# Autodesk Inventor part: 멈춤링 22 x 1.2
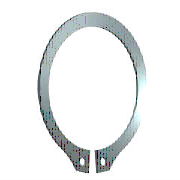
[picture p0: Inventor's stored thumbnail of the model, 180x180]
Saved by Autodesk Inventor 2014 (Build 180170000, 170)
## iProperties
IsCustomPart: 0
Created: 2009-02
Part Number: 멈춤링 22 x 1.2
Material: Steel, Mild
Description: 리테이닝 링(C형)
Document SubType Name: Modeling
Standard: KS B 1336
Designer: SeoGD™
Standards Organization: KS
Language: ko-KR
Size Designation: 22 x 1.2
Categories: <MemberInstance><Categories><Category DisplayName="샤프트 부품" InternalName="7f7aeb1f-a693-4053-b835-cee3144e0d98" Mnemonic="SHFT"><Category DisplayName="써클립" Inter
Density: 7.86 g/cm^3
Mass: 1.8286 g
Surface Area: 5.91219 cm^2
Volume: 0.232646 cm^3
Appearance: Metal-Steel
Author: SeoGD™
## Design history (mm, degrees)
sketch "스케치1"
  geometry: L1 (-6, 0)-(6, 0) reference; L2 (0, 20.189)-(0, -80.536) reference; L3 (-48.09, 0)-(48.09, 0) reference; L4 (-0.5, -21.488)-(-0.5, -25.588); L5 (-0.5, -6.54)-(-0.5, -13.29); L6 (-2.795, 2.7)-(3.672, 2.7); L7 (0.5, -6.54)-(0.5, -13.29); L8 (0.5, -21.488)-(0.5, -25.588); C1 r 1 at (-2, -23.437); C2 r 1 at (2, -23.437); A1 r 10.5 centre (0, -11) between (0.5, -21.488) and (-0.5, -21.488); A2 r 13.025 centre (0, -10.325) between (5.149, -22.289) and (-5.149, -22.289); A3 r 14.597 centre (0, -11) between (-2.318, -25.411) and (-0.5, -25.588); A4 r 2 centre (-2, -23.437) between (-3.97, -23.781) and (-2.318, -25.411); A5 r 2 centre (-5.94, -24.126) between (-3.97, -23.781) and (-5.149, -22.289); A6 r 2 centre (5.94, -24.126) between (5.149, -22.289) and (3.97, -23.781); A7 r 2 centre (2, -23.437) between (2.318, -25.411) and (3.97, -23.781); A8 r 14.597 centre (0, -11) between (0.5, -25.588) and (2.318, -25.411)
  constraints: 16 point on circle, 12 end point, 10 centre point, 9 symmetric about line, 5 point on line, 4 tangent, 3 coincident, 2 horizontal, 1 perpendicular, 1 vertical, 5 other
  dimensions: "d0" = 21 diameter of A1 (= ND); "d1" = 4.1 distance of L4.end L4.start (= SRB2); "d6" = 0.5 distance between parallel lines of L2 L5 (= 0.25 x SD5); "d7" = 2.7 distance between parallel lines of L6 L3 (= SRB1); "d8" = 0.675 distance of A1.centre A2.centre (= 0.25 x SRB1); "d9" = 2 radius of A4 (= SD5); "d10" = 2 radius of A5 (= SD5); "d11" = 1.5 distance from line of L4 A4.centre (= 0.75 x SD5); "d12" = 2 diameter of C1 (= SD5); "d13" = 2 diameter of C2 (= SD5); "d14" = 11 distance from line of A1.centre L1 (= 0.5 x WD)
extrude "본체" new body sketch "스케치1" distance "d2" = 1.2 (= SD); taper "d3" = 0 deg
workaxis "Work Axis1"
workplane "Work Plane1"
body "Solid1"
other parameters: "WD" = 22 (= WDMIN) [user parameter; used in 1 equation term], "SD" = 1.2 [user parameter; used in 1 equation term], "SRB1" = 2.7 [user parameter; used in 2 equation terms], "ND" = 21 [user parameter; used in 1 equation term], "SRB2" = 4.1 [user parameter; used in 1 equation term], "SD5" = 2 [user parameter; used in 6 equation terms], "d15" = 0, "d16" = 0, "d17" = 0, "d41" = 0, "d42" = 0, "WDMIN" = 22 [user parameter; used in 1 equation term], "SD3" = 20.5 [user parameter], "WDMAX" = 24 [user parameter]
